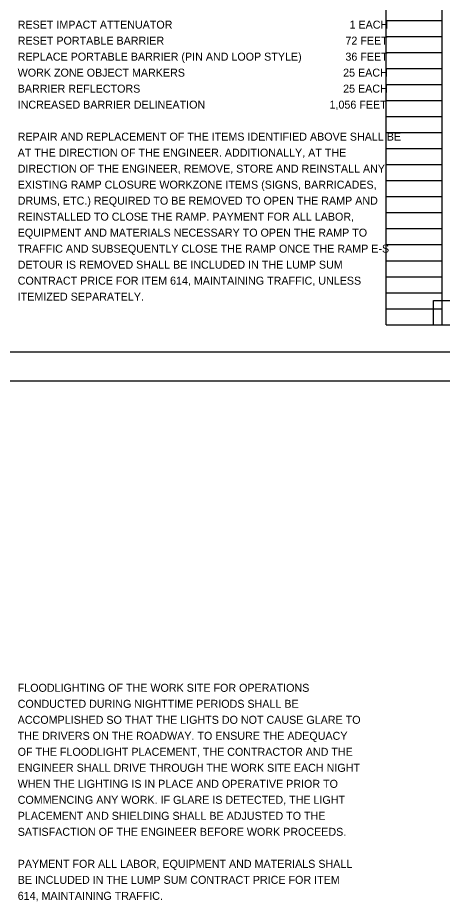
# Model space of a CAD drawing. Extents: x 0 to 34, y -9.1 to 22.
# Drawn here: x 17.24 to 24.66, y -9.11 to 6.35 of the extents above; entities that cross this region are included whole.
import ezdxf

# ---------------------------------------------------------------- set-up
doc = ezdxf.new("R2010")
doc.units = 0
for name, color, linetype in [('SC_Scratch1', 7, 'Continuous'), ('SH_Border', 7, 'Continuous'), ('SH_Cut_Line', 7, 'Continuous'), ('SH_Data', 7, 'Continuous'), ('SH_Text', 7, 'Continuous')]:
    doc.layers.add(name, color=color, linetype=linetype)

msp = doc.modelspace()

# ---------------------------------------------------------------- linework, layer by layer
at = {"layer": 'SC_Scratch1'}
msp.add_lwpolyline([(24.504, 1.402), (31.303, 1.402), (31.303, 0.97), (24.504, 0.97)], close=True, dxfattribs=at)
at = {"layer": 'SH_Border'}
msp.add_lwpolyline([(1.5, 21.5), (33.5, 21.5), (33.5, 0.5), (1.5, 0.5)], close=True, dxfattribs=at)
at = {"layer": 'SH_Cut_Line'}
msp.add_lwpolyline([(0, 0), (34, 0), (34, 22), (0, 22)], close=True, dxfattribs=at)
at = {"layer": 'SH_Data'}
for p, q in [((23.68, 0.98), (23.68, 21.14)), ((24.66, 0.98), (24.66, 21.14)), ((23.68, 6.3), (24.66, 6.3)), ((23.68, 6.02), (24.66, 6.02)), ((23.68, 5.74), (24.66, 5.74)), ((23.68, 5.46), (24.66, 5.46)), ((23.68, 5.18), (24.66, 5.18)), ((23.68, 4.9), (24.66, 4.9)), ((23.68, 4.62), (24.66, 4.62)), ((23.68, 4.34), (24.66, 4.34)), ((23.68, 4.06), (24.66, 4.06)), ((23.68, 3.78), (24.66, 3.78)), ((23.68, 3.5), (24.66, 3.5)), ((23.68, 3.22), (24.66, 3.22)), ((23.68, 2.94), (24.66, 2.94)), ((23.68, 2.66), (24.66, 2.66)), ((23.68, 2.38), (24.66, 2.38)), ((23.68, 2.1), (24.66, 2.1)), ((23.68, 1.82), (24.66, 1.82)), ((23.68, 1.54), (24.66, 1.54)), ((23.68, 1.26), (24.66, 1.26)), ((23.68, 0.98), (24.66, 0.98))]:
    msp.add_line(p, q, dxfattribs=at)

# ---------------------------------------------------------------- texts
at = {"layer": 'SH_Text'}
for s, p in [('RESET IMPACT ATTENUATOR', (17.24, 6.16)), ('1 EACH', (23.039, 6.16)), ('RESET PORTABLE BARRIER', (17.24, 5.88)), ('72 FEET', (22.967, 5.88)), ('REPLACE PORTABLE BARRIER (PIN AND LOOP STYLE)', (17.24, 5.6)), ('36 FEET', (22.967, 5.6)), ('WORK ZONE OBJECT MARKERS', (17.24, 5.32)), ('25 EACH', (22.927, 5.32)), ('BARRIER REFLECTORS', (17.24, 5.04)), ('25 EACH', (22.927, 5.04)), ('INCREASED BARRIER DELINEATION', (17.24, 4.76)), ('1,056 FEET', (22.689, 4.76)), ('REPAIR AND REPLACEMENT OF THE ITEMS IDENTIFIED ABOVE SHALL BE ', (17.24, 4.2)), ('AT THE DIRECTION OF THE ENGINEER. ADDITIONALLY, AT THE ', (17.24, 3.92)), ('DIRECTION OF THE ENGINEER, REMOVE, STORE AND REINSTALL ANY ', (17.24, 3.64)), ('EXISTING RAMP CLOSURE WORKZONE ITEMS (SIGNS, BARRICADES, ', (17.24, 3.36)), ('DRUMS, ETC.) REQUIRED TO BE REMOVED TO OPEN THE RAMP AND ', (17.24, 3.08)), ('REINSTALLED TO CLOSE THE RAMP. PAYMENT FOR ALL LABOR, ', (17.24, 2.8)), ('EQUIPMENT AND MATERIALS NECESSARY TO OPEN THE RAMP TO ', (17.24, 2.52)), ('TRAFFIC AND SUBSEQUENTLY CLOSE THE RAMP ONCE THE RAMP E-S ', (17.24, 2.24)), ('DETOUR IS REMOVED SHALL BE INCLUDED IN THE LUMP SUM ', (17.24, 1.96)), ('CONTRACT PRICE FOR ITEM 614, MAINTAINING TRAFFIC, UNLESS ', (17.24, 1.68)), ('ITEMIZED SEPARATELY.', (17.24, 1.4)), ('FLOODLIGHTING OF THE WORK SITE FOR OPERATIONS', (17.24, -5.444)), ('CONDUCTED DURING NIGHTTIME PERIODS SHALL BE', (17.24, -5.724)), ('ACCOMPLISHED SO THAT THE LIGHTS DO NOT CAUSE GLARE TO', (17.24, -6.004)), ('THE DRIVERS ON THE ROADWAY. TO ENSURE THE ADEQUACY', (17.24, -6.284)), ('OF THE FLOODLIGHT PLACEMENT, THE CONTRACTOR AND THE', (17.24, -6.564)), ('ENGINEER SHALL DRIVE THROUGH THE WORK SITE EACH NIGHT', (17.24, -6.844)), ('WHEN THE LIGHTING IS IN PLACE AND OPERATIVE PRIOR TO', (17.24, -7.124)), ('COMMENCING ANY WORK. IF GLARE IS DETECTED, THE LIGHT', (17.24, -7.404)), ('PLACEMENT AND SHIELDING SHALL BE ADJUSTED TO THE', (17.24, -7.684)), ('SATISFACTION OF THE ENGINEER BEFORE WORK PROCEEDS.', (17.24, -7.964)), ('PAYMENT FOR ALL LABOR, EQUIPMENT AND MATERIALS SHALL', (17.24, -8.524)), ('BE INCLUDED IN THE LUMP SUM CONTRACT PRICE FOR ITEM', (17.24, -8.804)), ('614, MAINTAINING TRAFFIC.', (17.24, -9.084))]:
    msp.add_text(s, height=0.14, dxfattribs=at).set_placement(p)

doc.saveas('drawing.dxf')
